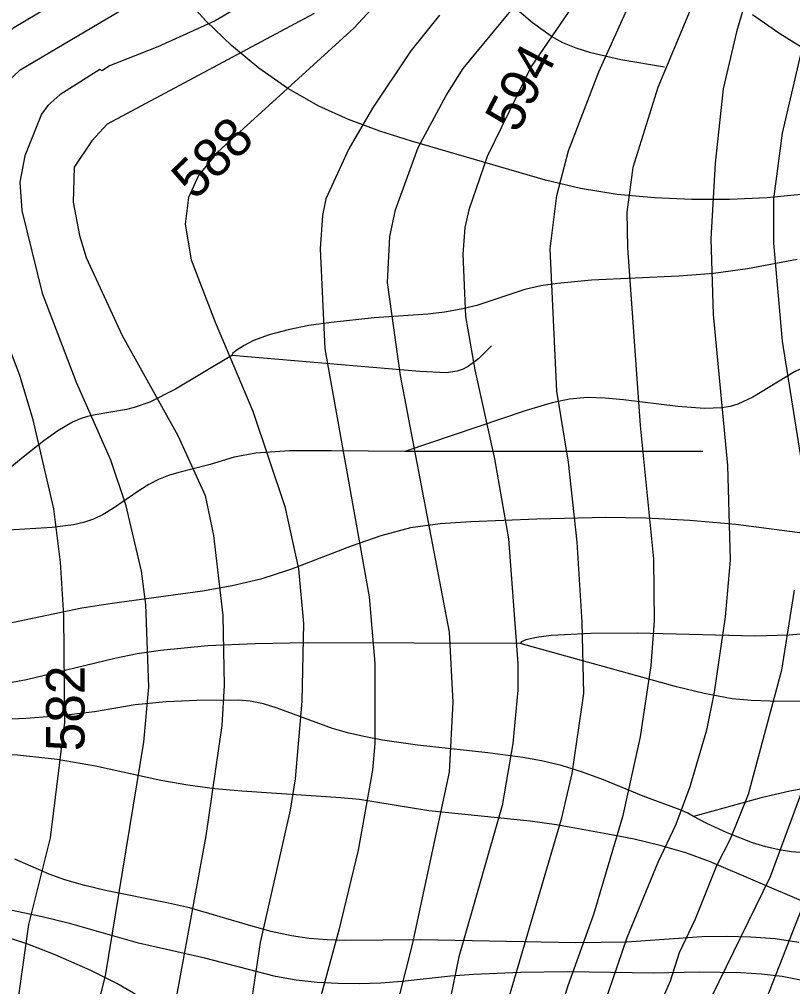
# Model space of a CAD drawing. Extents: x -709584 to -702006, y -1161789 to -1157496.
# Drawn here: x -708577.2 to -708376.2, y -1159891.3 to -1159639.5 of the extents above; entities that cross this region are included whole.
import ezdxf

# ---------------------------------------------------------------- set-up
doc = ezdxf.new("R2010")
doc.units = 0
for name, color, linetype in [('120_vrstevnice hlavní', 7, 'Continuous'), ('121_vrstevnice hlavní_popis', 7, 'Continuous'), ('122_vrstevnice základní', 7, 'Continuous'), ('411_akumulovaný odtok', 7, 'Continuous')]:
    doc.layers.add(name, color=color, linetype=linetype)

msp = doc.modelspace()

# ---------------------------------------------------------------- linework, layer by layer
at = {"layer": '120_vrstevnice hlavní'}
for points in [[(-708386.46, -1159628.06), (-708390.8, -1159642.82), (-708394.27, -1159657.57), (-708396.3, -1159676.95), (-708397.45, -1159696.63), (-708396.88, -1159716.3), (-708393.12, -1159755.64), (-708392.39, -1159780.23), (-708393.69, -1159794.98), (-708396.59, -1159814.66), (-708398.61, -1159824.49), (-708402.95, -1159839.25), (-708406.57, -1159849.08), (-708411.2, -1159858.92), (-708419.3, -1159878.59), (-708427.68, -1159903.18)], [(-708591.57, -1159840.69), (-708584.48, -1159810.32), (-708581.59, -1159792.96), (-708581.73, -1159779.94), (-708584.05, -1159758.24), (-708591.28, -1159727.87), (-708597.16, -1159697.97), (-708596.77, -1159681.58), (-708595.76, -1159673.48), (-708593.74, -1159665.96), (-708588.96, -1159654.68), (-708585.49, -1159648.46), (-708578.69, -1159641.61), (-708560.32, -1159630.67)], [(-708468.04, -1159638.48), (-708475.42, -1159647.74), (-708485.4, -1159662.63), (-708491.62, -1159673.19), (-708497.55, -1159686.21), (-708498.42, -1159690.55), (-708498.99, -1159699.23), (-708497.84, -1159725.27), (-708486.27, -1159789.78), (-708484.82, -1159807.13), (-708484.82, -1159827.96), (-708485.4, -1159834.91), (-708489.16, -1159855.74), (-708494.22, -1159876.56), (-708503.62, -1159911.28)]]:
    msp.add_lwpolyline(points, dxfattribs=at)
at = {"layer": '122_vrstevnice základní'}
for points in [[(-708458.21, -1159607.24), (-708490.32, -1159641.81), (-708525.75, -1159674.06), (-708530.67, -1159680.14), (-708533.28, -1159685.92), (-708534.14, -1159692.86), (-708532.55, -1159702.12), (-708526.33, -1159718.32), (-708516.5, -1159741.47), (-708508.25, -1159766.34), (-708504.64, -1159782.54), (-708503.33, -1159796.72), (-708503.77, -1159816.97), (-708505.5, -1159837.22), (-708506.81, -1159845.32), (-708514.62, -1159879.75), (-708518.23, -1159904.05)], [(-708524.02, -1160101.49), (-708491.33, -1160075.45), (-708469.92, -1160060.7), (-708465.29, -1160058.24), (-708455.02, -1160050.72), (-708440.56, -1160037.12), (-708432.02, -1160025.55), (-708421.9, -1160007.03), (-708410.76, -1159979.26), (-708404.98, -1159960.75), (-708398.47, -1159942.52), (-708385.45, -1159900.86), (-708373.73, -1159870.78), (-708363.9, -1159852.26), (-708354.35, -1159829.12), (-708349.87, -1159812.92), (-708345.96, -1159782.83), (-708346.1, -1159755.06), (-708350.16, -1159704.15), (-708349.58, -1159685.63), (-708347.7, -1159671.75), (-708342.63, -1159646.58), (-708332.22, -1159607.24)], [(-708392.39, -1159612.15), (-708411.2, -1159657.28), (-708417.7, -1159678.11), (-708419.3, -1159689.68), (-708419.15, -1159698.94), (-708415.82, -1159745.23), (-708412.35, -1159779.94), (-708412.21, -1159796.14), (-708413.08, -1159807.71), (-708415.82, -1159826.23), (-708420.45, -1159847.06), (-708427.97, -1159872.51), (-708434.63, -1159891.03), (-708441.14, -1159911.86)], [(-708585.93, -1160082.25), (-708557.29, -1160060.7), (-708526.04, -1160039), (-708508.11, -1160024.97), (-708500.3, -1160018.03), (-708489.01, -1160006.45), (-708479.9, -1159994.88), (-708473.97, -1159986.2), (-708468.62, -1159974.63), (-708461.53, -1159950.04), (-708449.82, -1159893.63), (-708436.22, -1159847.34), (-708433.47, -1159835.77), (-708430.43, -1159814.95), (-708430.87, -1159796.43), (-708432.17, -1159775.6), (-708434.48, -1159754.77), (-708437.52, -1159736.26), (-708439.26, -1159699.23), (-708437.52, -1159685.34), (-708434.48, -1159673.77), (-708426.53, -1159653.23), (-708413.08, -1159623.15)], [(-708368.38, -1159624.01), (-708378.94, -1159669.14), (-708381.11, -1159686.21), (-708381.11, -1159697.78), (-708378.94, -1159723.24), (-708374.17, -1159753.33)], [(-708578.12, -1159898.55), (-708574.79, -1159875.12), (-708569.15, -1159852.55), (-708565.39, -1159822.47), (-708565.68, -1159794.7), (-708566.54, -1159780.81), (-708568.28, -1159766.92), (-708573.63, -1159743.78), (-708577.1, -1159732.21), (-708581.59, -1159720.35), (-708583.9, -1159709.06), (-708587.52, -1159697.49), (-708589.11, -1159688.24), (-708589.11, -1159681.29), (-708587.09, -1159666.13), (-708584.07, -1159659.28), (-708577.01, -1159652.67), (-708532.12, -1159626.04)], [(-708627.29, -1160082.54), (-708610.95, -1160069.66), (-708554.39, -1160030.75), (-708540.07, -1160019.76), (-708525.9, -1160007.47), (-708517.8, -1159998.79), (-708510.71, -1159989.68), (-708501.6, -1159975.65), (-708497.26, -1159966.53), (-708494.22, -1159958.43), (-708490.03, -1159943.97), (-708483.08, -1159912.15), (-708474.98, -1159880.32), (-708465.44, -1159835.48), (-708464.42, -1159817.26), (-708465.44, -1159799.03), (-708478.17, -1159732.21), (-708481.49, -1159708.05), (-708480.91, -1159696.05), (-708479.47, -1159689.1), (-708473.54, -1159672.9), (-708466.31, -1159659.31), (-708461.82, -1159652.36), (-708446.2, -1159633.27)], [(-708431.16, -1159632.69), (-708444.17, -1159651.79), (-708455.6, -1159675.22), (-708460.37, -1159689.1), (-708461.39, -1159693.73), (-708461.96, -1159700.68), (-708461.24, -1159716.88), (-708458.78, -1159730.76), (-708453.72, -1159753.91), (-708450.1, -1159774.73), (-708447.65, -1159807.13), (-708447.65, -1159814.08), (-708448.95, -1159827.96), (-708451.7, -1159844.16), (-708462.98, -1159883.51), (-708468.19, -1159908.96)], [(-708520.69, -1159636.6), (-708526.33, -1159639.93), (-708541.23, -1159646.72), (-708553.82, -1159651.64), (-708555.7, -1159652.94), (-708556.35, -1159652.56), (-708566.69, -1159659.16), (-708569.87, -1159661.91), (-708571.46, -1159664.23), (-708575.85, -1159675.08), (-708577.12, -1159681.93), (-708576.61, -1159689.27), (-708571.32, -1159710.8), (-708562.49, -1159733.94), (-708553.53, -1159754.19), (-708549.62, -1159765.77), (-708545.57, -1159783.12), (-708544.41, -1159791.8), (-708543.69, -1159813.21), (-708544.99, -1159827.67), (-708554.97, -1159888.42), (-708564.37, -1159926.03)], [(-708500.59, -1159638.04), (-708554.39, -1159666.77), (-708558.43, -1159671.18), (-708562.96, -1159678.03), (-708563.22, -1159687.08), (-708561.62, -1159695.76), (-708559.89, -1159701.54), (-708550.49, -1159721.79), (-708536.02, -1159747.83), (-708528.94, -1159763.45), (-708526.77, -1159773.87), (-708524.31, -1159794.7), (-708524.02, -1159812.92), (-708524.6, -1159823.33), (-708528.79, -1159851.97), (-708537.33, -1159898.84)], [(-708356.81, -1159637.9), (-708361.87, -1159658.73), (-708364.19, -1159676.95), (-708364.04, -1159708.2), (-708362.74, -1159721.22), (-708359.7, -1159768.08), (-708360.43, -1159784.86), (-708364.33, -1159808), (-708367.08, -1159819.57), (-708371.42, -1159834.04), (-708381.98, -1159862.68), (-708397.31, -1159893.92), (-708402.52, -1159906.94), (-708405.99, -1159917.35), (-708415.97, -1159956.41), (-708424.36, -1159985.05), (-708429.57, -1159998.06), (-708436.65, -1160011.08), (-708449.53, -1160029.31), (-708463.7, -1160043.05), (-708484.39, -1160059.11), (-708495.96, -1160066.77), (-708512.16, -1160078.78)], [(-708375.76, -1159788.04), (-708379.08, -1159808.87), (-708387.76, -1159841.27), (-708392.39, -1159852.84), (-708396.01, -1159859.78), (-708401.5, -1159873.67), (-708405.71, -1159882.42), (-708408.01, -1159889.87), (-708411.05, -1159896.81), (-708420.41, -1159920.28), (-708426.96, -1159947.44), (-708436.07, -1159977.53), (-708445.62, -1160000.67), (-708455.75, -1160018.03), (-708462.69, -1160026.7), (-708478.89, -1160043.19), (-708488.29, -1160051.15), (-708524.71, -1160075.55), (-708539.08, -1160085.83)]]:
    msp.add_lwpolyline(points, dxfattribs=at)
at = {"layer": '411_akumulovaný odtok'}
msp.add_line((-708399.49, -1159752), (-708476.99, -1159752), dxfattribs=at)
for points in [[(-708409.49, -1159652), (-708420.89, -1159650.08), (-708428.67, -1159648.23), (-708432.46, -1159647.03), (-708435.91, -1159645.62), (-708438.86, -1159644.02), (-708443.8, -1159640.42), (-708448.53, -1159636.43), (-708480.76, -1159606.66), (-708487.78, -1159600.59), (-708492.63, -1159596.95), (-708495.15, -1159595.37), (-708497.77, -1159594.04), (-708500.4, -1159593.06), (-708511.52, -1159590.29), (-708514.39, -1159589.43), (-708521.11, -1159586.86), (-708531.95, -1159581.97), (-708541.99, -1159577)], [(-708266.99, -1159672), (-708267.71, -1159672.47), (-708271.74, -1159673.3), (-708278.78, -1159674.21), (-708324.86, -1159678.49), (-708337.8, -1159679.87), (-708350.07, -1159681.46), (-708373.09, -1159685), (-708382.81, -1159685.95), (-708392.58, -1159686.42), (-708402.36, -1159686.44), (-708412.1, -1159686.01), (-708421.77, -1159685.07), (-708431.32, -1159683.52), (-708440.44, -1159681.36), (-708475.28, -1159671.22), (-708483.55, -1159668.59), (-708491.63, -1159665.62), (-708499.42, -1159662.11), (-708507.4, -1159657.53), (-708514.94, -1159652.23), (-708522.08, -1159646.33), (-708528.78, -1159639.92), (-708549.27, -1159617.28)], [(-708207.75, -1159637.25), (-708233.17, -1159644.62), (-708242.14, -1159646.94), (-708250.27, -1159648.7), (-708258.1, -1159650.08), (-708265.44, -1159651.11), (-708286.41, -1159653.34), (-708325.29, -1159656.64), (-708333.67, -1159657.11), (-708341.96, -1159656.96), (-708349.71, -1159655.99), (-708357.31, -1159654.19), (-708364.68, -1159651.55), (-708372.22, -1159647.81), (-708379.5, -1159643.33), (-708386.61, -1159638.32)], [(-708375, -1159701.99), (-708387.9, -1159704.45), (-708396.76, -1159705.7), (-708405.81, -1159706.38), (-708428.46, -1159707.4), (-708437.3, -1159708.23), (-708441.61, -1159708.91), (-708445.8, -1159709.87), (-708458.25, -1159713.97), (-708462.41, -1159714.98), (-708466.69, -1159715.71), (-708471.05, -1159716.24), (-708484.95, -1159717.24), (-708496.21, -1159718.38), (-708501.95, -1159719.24), (-708507.39, -1159720.32), (-708512.28, -1159721.63), (-708516.37, -1159723.14), (-708518.83, -1159724.38), (-708520.63, -1159725.53), (-708521.71, -1159726.44), (-708521.99, -1159727)], [(-708454.49, -1159724.5), (-708457.85, -1159727.86), (-708460.45, -1159729.8), (-708461.87, -1159730.56), (-708463.4, -1159731.12), (-708466.23, -1159731.49), (-708473.12, -1159731.15), (-708521.99, -1159727)], [(-708521.99, -1159727), (-708536.63, -1159735.79), (-708543.32, -1159739.14), (-708547.41, -1159740.58), (-708549.42, -1159741.05), (-708557.55, -1159742.43), (-708559.54, -1159742.89), (-708561.46, -1159743.51), (-708563.44, -1159744.37), (-708567.23, -1159746.61), (-708570.88, -1159749.22), (-708576.24, -1159753.46), (-708616.99, -1159787)], [(-708361.99, -1159727), (-708363.21, -1159726.93), (-708366.22, -1159727.42), (-708370.59, -1159728.84), (-708375.73, -1159731.3), (-708386.56, -1159737.81), (-708390.43, -1159739.64), (-708392.44, -1159740.26), (-708394.61, -1159740.64), (-708399.11, -1159740.81), (-708406.07, -1159740.27), (-708420.19, -1159738.54), (-708424.88, -1159738.11), (-708429.55, -1159737.98), (-708434.16, -1159738.39), (-708438.72, -1159739.34), (-708445.5, -1159741.31), (-708476.99, -1159752)], [(-708476.99, -1159752), (-708496.05, -1159751.78), (-708507.04, -1159751.85), (-708515.8, -1159752.45), (-708521.39, -1159753.45), (-708527.67, -1159755.35), (-708535.8, -1159757.45), (-708538.46, -1159758.26), (-708541.04, -1159759.27), (-708543.54, -1159760.57), (-708545.94, -1159762.07), (-708553.02, -1159766.92), (-708555.45, -1159768.37), (-708557.98, -1159769.57), (-708560.54, -1159770.43), (-708563.2, -1159771.04), (-708568.73, -1159771.76), (-708585.89, -1159772.79)], [(-708363.01, -1159774.6), (-708390.94, -1159771), (-708402.89, -1159769.96), (-708414.33, -1159769.37), (-708424.76, -1159769.19), (-708442.73, -1159769.58), (-708459.86, -1159770.32), (-708467.8, -1159770.82), (-708475.54, -1159771.87), (-708483.29, -1159773.9), (-708490.97, -1159776.61), (-708506.47, -1159782.61), (-708514.46, -1159785.19), (-708521.95, -1159786.97), (-708529.62, -1159788.33), (-708553.14, -1159791.51), (-708561.01, -1159792.79), (-708579.17, -1159796.59)], [(-708362.36, -1159798.47), (-708377.1, -1159799.81), (-708386.09, -1159800.06), (-708416.64, -1159799.29), (-708428.64, -1159799.33), (-708438.93, -1159799.88), (-708442.82, -1159800.39), (-708445.54, -1159801.03), (-708446.69, -1159801.55), (-708446.99, -1159802)], [(-708446.99, -1159802), (-708502.33, -1159801.81), (-708515.82, -1159802.04), (-708528.23, -1159802.6), (-708540.51, -1159803.75), (-708546.58, -1159804.67), (-708552.43, -1159805.85), (-708575.4, -1159811.4), (-708581.06, -1159812.48)], [(-708321.99, -1159817), (-708323.25, -1159817.72), (-708326.59, -1159818.76), (-708328.84, -1159819.17), (-708331.38, -1159819.37), (-708334.1, -1159819.37), (-708339.71, -1159818.9), (-708347.11, -1159817.81), (-708352.03, -1159817.35), (-708359.49, -1159817.1), (-708381.98, -1159817), (-708386.96, -1159816.8), (-708391.9, -1159816.34), (-708399.15, -1159815), (-708406.35, -1159813.21), (-708446.99, -1159802)], [(-708401.99, -1159847), (-708403.47, -1159846.1), (-708405.44, -1159845.27), (-708415, -1159841.7), (-708425.34, -1159837.48), (-708430.83, -1159835.41), (-708436.27, -1159833.73), (-708441.51, -1159832.46), (-708446.29, -1159831.6), (-708455.39, -1159830.43), (-708473.75, -1159828.4), (-708482.81, -1159827.11), (-708487.25, -1159826.29), (-708491.61, -1159825.31), (-708495.86, -1159824.11), (-708510.23, -1159818.75), (-708513.73, -1159817.69), (-708517.24, -1159816.97), (-708520.25, -1159816.71), (-708531.06, -1159816.76), (-708539.07, -1159817.16), (-708547.14, -1159817.93), (-708557.71, -1159819.7), (-708566.54, -1159820.82), (-708575.6, -1159821.46), (-708594.96, -1159822.31)], [(-708372.62, -1159869.46), (-708397.76, -1159858.73), (-708403.92, -1159856.46), (-708410.6, -1159854.5), (-708417.4, -1159852.91), (-708424.26, -1159851.55), (-708437.56, -1159849.17), (-708444.4, -1159848.19), (-708470.74, -1159845.55), (-708488.77, -1159842.59), (-708493.65, -1159842.11), (-708519.41, -1159840.42), (-708526.45, -1159839.75), (-708533.48, -1159838.85), (-708540.44, -1159837.63), (-708557.47, -1159833.85), (-708567.43, -1159832.13), (-708577.71, -1159831.06), (-708588.08, -1159830.54), (-708598.09, -1159830.45), (-708607.29, -1159830.64), (-708615.23, -1159831.01), (-708621.46, -1159831.43), (-708626.99, -1159832)], [(-708256.99, -1159877), (-708290.73, -1159871.11), (-708299.75, -1159869.15), (-708305.56, -1159867.47), (-708308.36, -1159866.43), (-708311.06, -1159865.19), (-708313.57, -1159863.76), (-708323.09, -1159857.17), (-708325.51, -1159855.66), (-708328.01, -1159854.35), (-708330.59, -1159853.29), (-708341.32, -1159849.82), (-708346.69, -1159847.28), (-708357.16, -1159841.59), (-708359.82, -1159840.47), (-708362.54, -1159839.66), (-708365.17, -1159839.27), (-708367.87, -1159839.2), (-708373.54, -1159839.76), (-708376.9, -1159840.39), (-708384.34, -1159842.14), (-708401.99, -1159847)], [(-708362.54, -1159857.21), (-708376.46, -1159856.18), (-708379.71, -1159855.64), (-708383.13, -1159854.85), (-708386.6, -1159853.8), (-708393.17, -1159851.27), (-708398.46, -1159848.84), (-708401.99, -1159847)], [(-708374.57, -1159879.81), (-708380.75, -1159878.86), (-708387.05, -1159878.36), (-708393.4, -1159878.2), (-708399.76, -1159878.33), (-708419.33, -1159879.67), (-708432.65, -1159879.88), (-708472.95, -1159879.06), (-708492.56, -1159879.21), (-708497.21, -1159879.08), (-708501.85, -1159878.7), (-708506.47, -1159878.03), (-708511.8, -1159876.89), (-708517.1, -1159875.46), (-708533.05, -1159870.79), (-708538.47, -1159869.51), (-708554.83, -1159866.22), (-708560.19, -1159864.97), (-708565.43, -1159863.45), (-708569.54, -1159861.95), (-708578.42, -1159858.05)], [(-708496.99, -1159907), (-708498.2, -1159906.33), (-708501.54, -1159905.12), (-708506.7, -1159903.86), (-708513.06, -1159902.95), (-708529.34, -1159901.74), (-708533.96, -1159900.81), (-708536.15, -1159900.06), (-708540.04, -1159897.99), (-708547.59, -1159892.92), (-708551.91, -1159890.43), (-708558.69, -1159887.08), (-708567.97, -1159883), (-708575.02, -1159880.24), (-708579.78, -1159878.68), (-708584.58, -1159877.56), (-708594.13, -1159875.9), (-708596.51, -1159875.22), (-708599.11, -1159874.13), (-708601.83, -1159872.7), (-708607.3, -1159869.25), (-708612.15, -1159865.76), (-708616.99, -1159862)], [(-708373.67, -1159889.65), (-708378.92, -1159888.66), (-708384.26, -1159888.02), (-708389.65, -1159887.65), (-708400.44, -1159887.47), (-708412.3, -1159887.78), (-708434.75, -1159887.38), (-708446.94, -1159887.56), (-708459.11, -1159888.09), (-708465.14, -1159888.53), (-708477.74, -1159889.88), (-708483.26, -1159890.32), (-708488.8, -1159890.52), (-708494.34, -1159890.48), (-708499.85, -1159890.19), (-708505.29, -1159889.6), (-708510.64, -1159888.66), (-708528.98, -1159883.89), (-708546.31, -1159879.92), (-708563.88, -1159874.88), (-708571.33, -1159873.13), (-708594.82, -1159868.15)]]:
    msp.add_lwpolyline(points, dxfattribs=at)

# ---------------------------------------------------------------- texts
at = {"layer": '121_vrstevnice hlavní_popis'}
for s, rotation, p in [('594', 62.6786, (-708447.72, -1159669.44)), ('588', 44.4005, (-708531.62, -1159686.81)), ('582', 90.0017, (-708560.3, -1159830.02))]:
    msp.add_text(s, height=10, rotation=rotation, dxfattribs=at).set_placement(p)

doc.saveas('drawing.dxf')
